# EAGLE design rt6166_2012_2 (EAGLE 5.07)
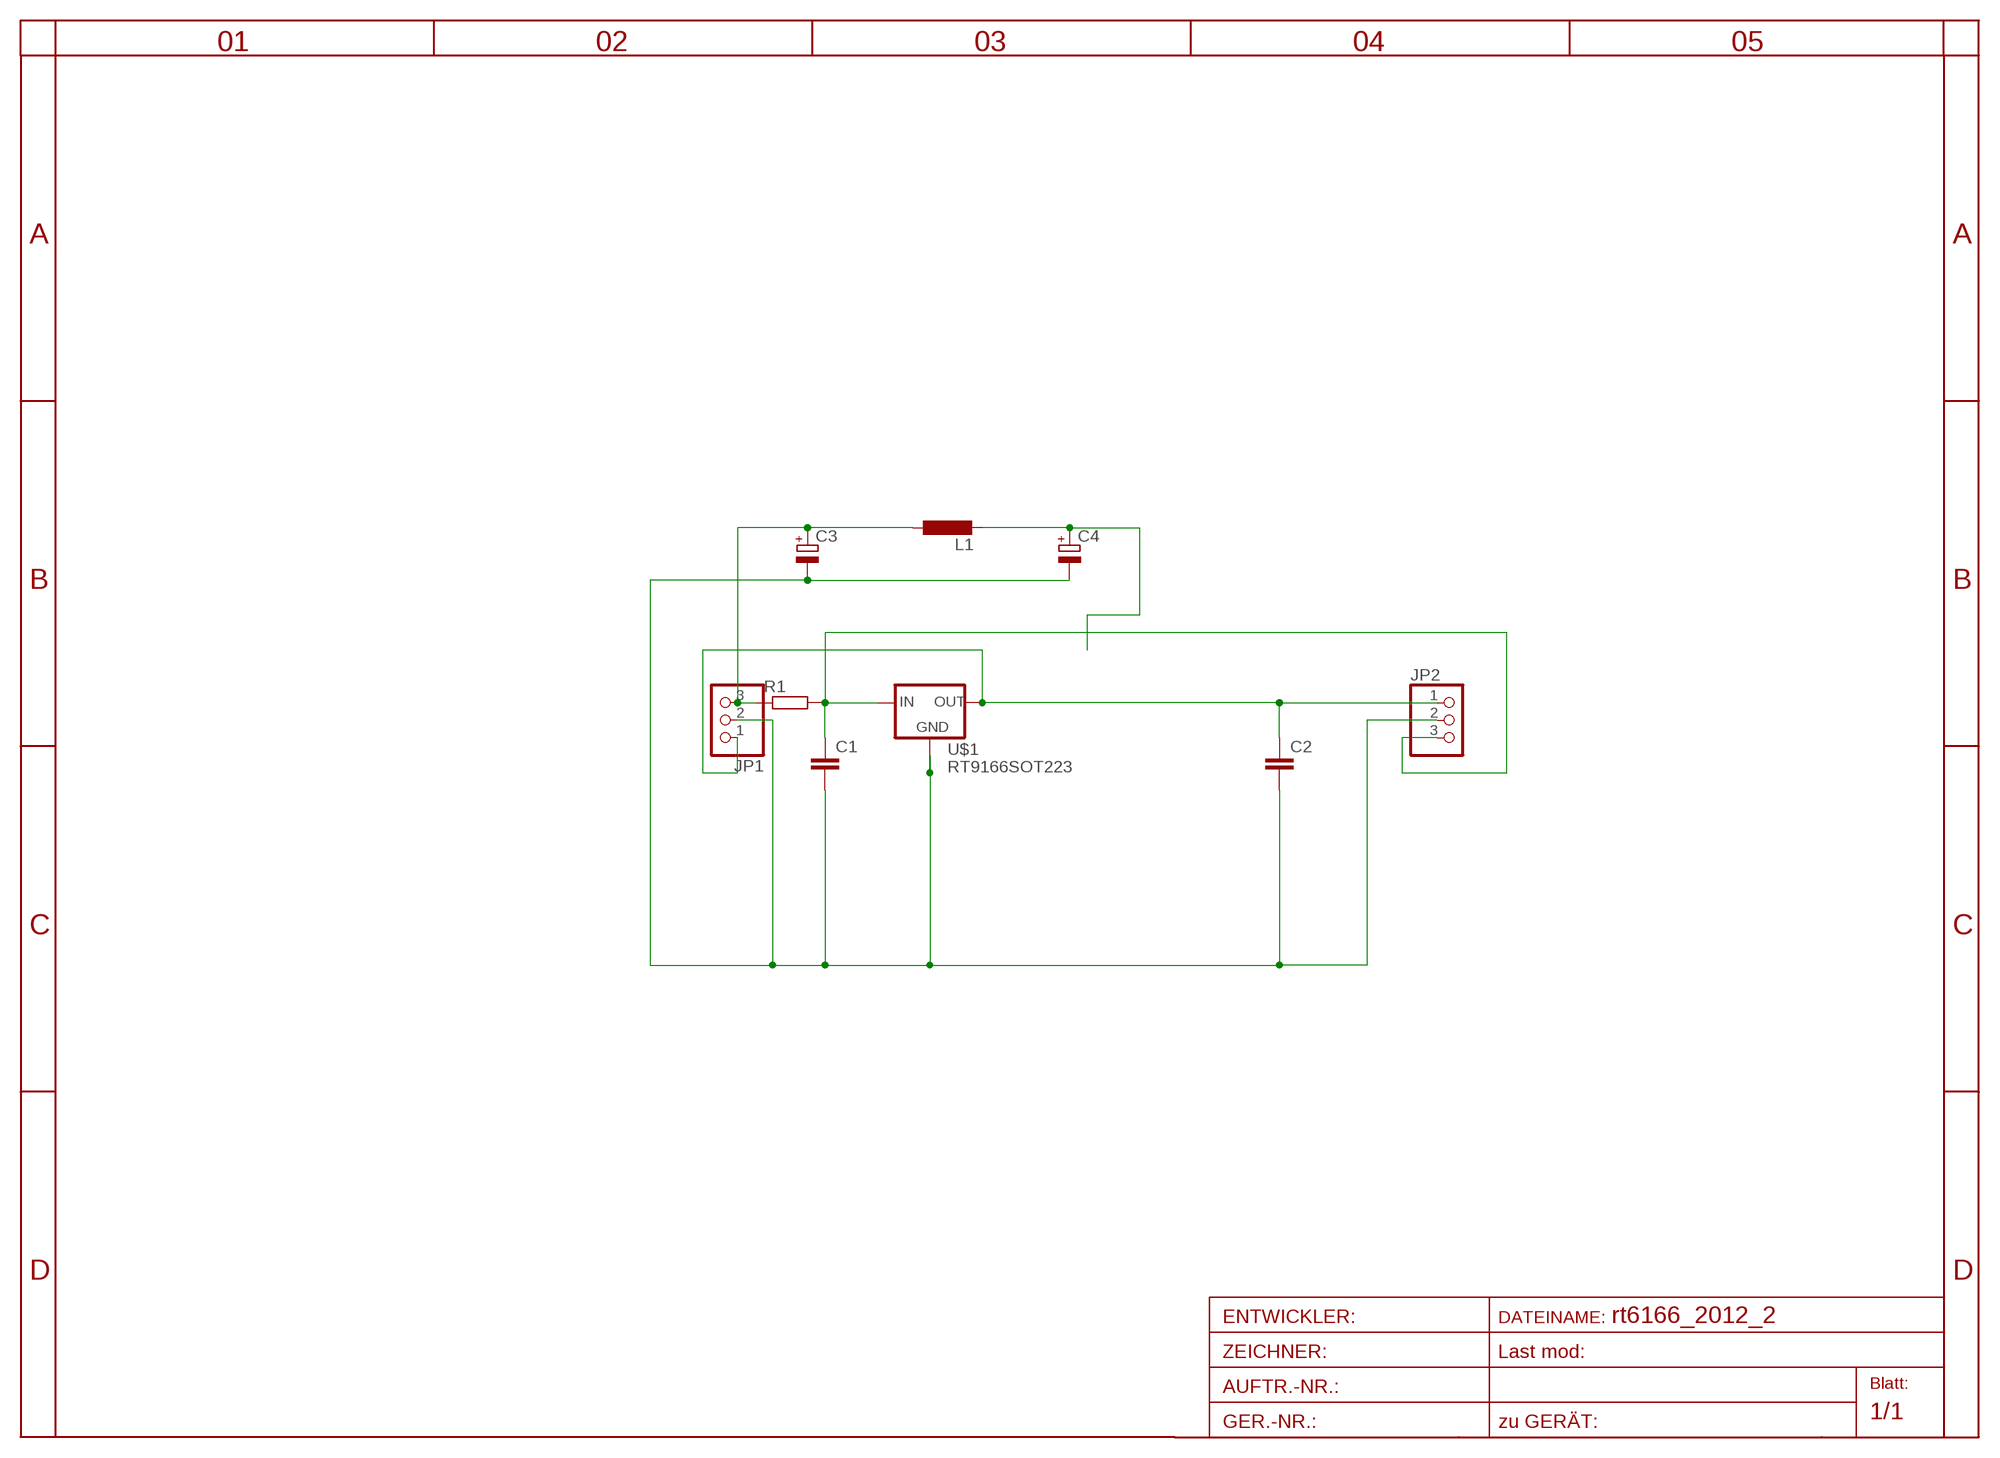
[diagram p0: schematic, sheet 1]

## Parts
C1  C-EUC1206  [C1206]
C2  C-EUC1206  [C1206]
C3  CPOL-EUC  [PANASONIC_C]
C4  CPOL-EUE2.5-7  [E2,5-7]
JP1  PINHD-1X3  [1X03]
JP2  PINHD-1X3  [1X03]
L1  L-EUPIS2816  [PIS2816]
R1  R-EU_M0805  [M0805]
U$1  RT9166SOT223  [SOT223]

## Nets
GND: C1.2 C2.2 C3.- C4.- JP1.2 JP2.2 U$1.2(GND) U$1.4(GND1)
IN: C2.1 JP1.1 JP2.1 U$1.1(OUT)
N$1: C3.+ JP1.3 L1.1 R1.1
N$3: C4.+ L1.2
OUT: C1.1 JP2.3 R1.2 U$1.3(IN)

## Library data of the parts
C1 C2 = rcl:C-EU: CAPACITOR, European symbol
C3 C4 = rcl-2:CPOL-EU: POLARIZED CAPACITOR, European symbol
JP1 JP2 = pinhead:PINHD-1X3: PIN HEADER
L1 = rcl:L-EU: INDUCTOR, European symbol
R1 = rcl:R-EU_: RESISTOR, European symbol
U$1 = v-reg:RT9166

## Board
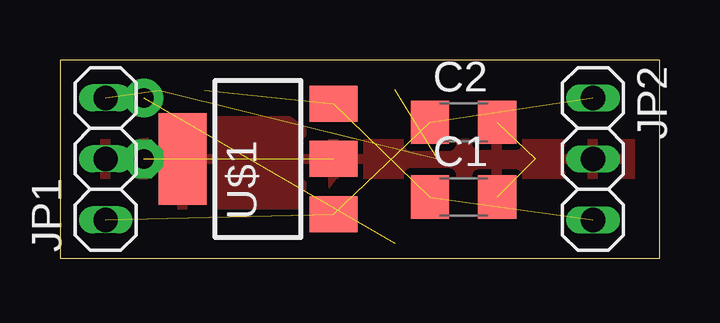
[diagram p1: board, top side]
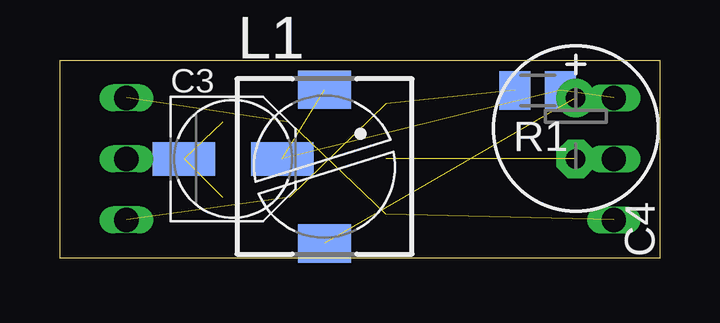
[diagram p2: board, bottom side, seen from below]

Size 25 x 8.25 mm. Coordinates in mm from the lower left corner, seen from the top.
Outline: 0,0 25,0 25,8.25 0,8.25 0,0
Copper layers (1*16): Top 0.035mm / dielectric 1.5mm / Bottom 0.035mm
Design rules "default": minimum track width 10mil, minimum drill 20mil, track to track 8mil, track to pad 8mil, pad to pad 8mil, via to via 8mil, smd to smd 8mil, copper to edge 40mil, drill to drill 8mil, minimum pad ring 1mil, minimum via ring 8mil, stop-mask expansion 4mil, vias tented up to drill 0mil, thermal gap 10mil

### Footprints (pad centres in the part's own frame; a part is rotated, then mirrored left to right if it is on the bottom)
C1206 = smd 1.6 x 1.8: 1 -1.4,0; 2 1.4,0
PANASONIC_C = smd 2.6 x 1.4: + 2.05,0; - -2.05,0
E2,5-7 = drill 0.813 pad 1.6 round: + -1.27,0 | drill 0.813 pad 1.6 octagon: - 1.27,0
1X03 = drill 1.016 long: 1 -2.54,0; 2 0,0; 3 2.54,0
PIS2816 = smd 2.2 x 1.6: 1 0,3.2; 2 0,-3.2
M0805 = smd 1.3 x 1.6: 1 -0.95,0; 2 0.95,0
SOT223 = smd 1.5 x 2: 1 -2.3,-3.15; 2 0,-3.15; 3 2.3,-3.15 | smd 3.8 x 2: 4 0,3.15

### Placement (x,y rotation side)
C1  16.83,2.54 0 top
C2  16.83,5.65 0 top
C3  17.78,4.13 0 bottom
C4  3.49,5.4 270 bottom
JP1  1.91,4.13 90 top
JP2  22.23,4.13 270 top
L1  13.97,3.81 0 bottom
R1  5.08,6.99 180 bottom
U$1  8.26,4.13 90 top

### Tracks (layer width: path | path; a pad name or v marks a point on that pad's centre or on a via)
GND  (3 unrouted)
  pour Top (isolate 0.305): 0.95,4.76 3.17,4.76 arc90 4.45,5.71 9.53,5.71 10.79,4.76 24.77,4.76 24.77,3.49 11.43,3.49 10.48,2.22 4.76,2.22 3.81,3.49 0.95,3.49
IN  (3 unrouted)
N$1  (3 unrouted)
N$3  (1 unrouted)
OUT  (3 unrouted)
